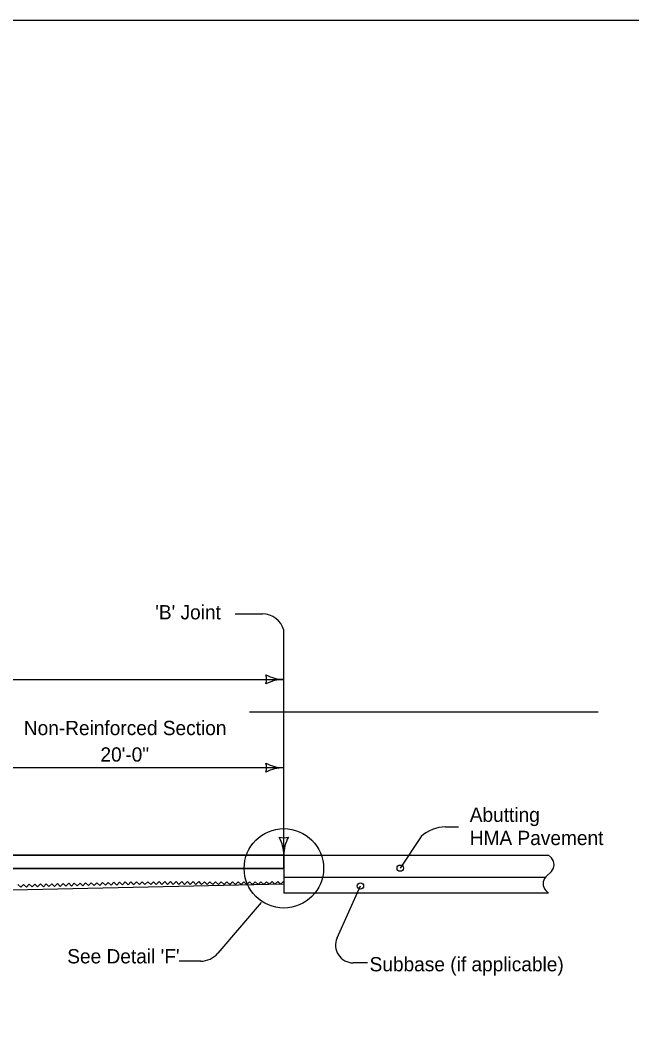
# Model space of a CAD drawing. Extents: x -2134934 to -2124557, y -2139046 to -2134021.
# Drawn here: x -2130115 to -2129429, y -2138178 to -2137036 of the extents above; entities that cross this region are included whole.
import ezdxf

# ---------------------------------------------------------------- set-up
doc = ezdxf.new("R2010")
doc.units = 0
for name, color, linetype in [('BridgeSuperStructureExisting', 7, 'Continuous'), ('dsnAlignmentStation', 7, 'Continuous'), ('dsnStdLabel', 7, 'Continuous'), ('TC_Barrier', 7, 'Continuous')]:
    doc.layers.add(name, color=color, linetype=linetype)

msp = doc.modelspace()

# ---------------------------------------------------------------- linework, layer by layer
at = {"layer": 'BridgeSuperStructureExisting'}
for p, q in [((-2129873.6, -2137701.5), (-2129843.1, -2137701.5)), ((-2129819.2, -2137972.1), (-2129819.2, -2137719.8)), ((-2130980.5, -2137775), (-2129819.2, -2137775)), ((-2129857.8, -2137811.5), (-2129466.9, -2137811.5)), ((-2130175.6, -2137874), (-2129819.2, -2137874)), ((-2129638.1, -2137940.5), (-2129623.3, -2137940.5)), ((-2129665.1, -2137951.1), (-2129688.8, -2137986.7)), ((-2130977.5, -2137972.1), (-2129819.2, -2137972.1)), ((-2129819.2, -2137972.1), (-2130175.6, -2137972.1)), ((-2129819.2, -2137986.9), (-2129819.2, -2137972.1)), ((-2129819.2, -2137972.1), (-2129522.4, -2137972.1)), ((-2129819.2, -2137972.1), (-2129819.2, -2137986.9)), ((-2129537, -2137972.1), (-2129537, -2137972.1)), ((-2129519.3, -2137975.2), (-2129522.4, -2137972.1)), ((-2129819.2, -2137986.9), (-2130977.5, -2137986.9)), ((-2130175.6, -2137986.9), (-2129819.2, -2137986.9)), ((-2129819.2, -2137986.9), (-2129819.2, -2138014.6)), ((-2129819.2, -2137996.8), (-2129525.8, -2137996.8)), ((-2129525.6, -2137996.6), (-2129519.3, -2137990.3)), ((-2129819.2, -2138004.6), (-2130943.9, -2138030)), ((-2129759.6, -2138065), (-2129733.3, -2138006.7)), ((-2129522.4, -2138014.8), (-2129525.6, -2138011.7)), ((-2129522.6, -2138014.6), (-2129819.2, -2138014.6)), ((-2129844.7, -2138025.1), (-2129893.3, -2138082.2)), ((-2129912.4, -2138091), (-2129936.6, -2138091)), ((-2129725.3, -2138092.9), (-2129741.5, -2138092.9))]:
    msp.add_line(p, q, dxfattribs=at)
for points in [[(-2130117.4, -2138005), (-2130114.2, -2138008.1), (-2130111.1, -2138004.9), (-2130107.8, -2138008), (-2130104.7, -2138004.7), (-2130101.5, -2138007.8), (-2130098.4, -2138004.6), (-2130095.2, -2138007.7), (-2130092.1, -2138004.4), (-2130088.8, -2138007.5), (-2130085.7, -2138004.3), (-2130082.5, -2138007.4), (-2130079.4, -2138004.1), (-2130076.2, -2138007.2), (-2130073.1, -2138004), (-2130069.8, -2138007.1), (-2130066.7, -2138003.8), (-2130065.1, -2138005.4)], [(-2130065.1, -2138005.4), (-2130063.5, -2138006.9), (-2130060.4, -2138003.7), (-2130057.2, -2138006.8), (-2130054.1, -2138003.5), (-2130050.8, -2138006.6), (-2130047.7, -2138003.4), (-2130044.5, -2138006.5), (-2130041.4, -2138003.2), (-2130038.2, -2138006.3), (-2130035.1, -2138003.1), (-2130031.8, -2138006.2), (-2130028.7, -2138003), (-2130025.5, -2138006), (-2130022.4, -2138002.8), (-2130019.2, -2138005.9), (-2130016.1, -2138002.7), (-2130012.8, -2138005.7), (-2130009.7, -2138002.5), (-2130006.5, -2138005.6), (-2130003.4, -2138002.4), (-2130000.2, -2138005.4), (-2129997.1, -2138002.2), (-2129993.8, -2138005.3), (-2129990.7, -2138002.1), (-2129989.1, -2138003.6)], [(-2129989.1, -2138003.5), (-2129987.5, -2138005), (-2129984.4, -2138001.9), (-2129981.2, -2138005), (-2129978, -2138001.9), (-2129974.9, -2138005), (-2129971.7, -2138001.9), (-2129968.5, -2138005), (-2129965.4, -2138001.9), (-2129962.2, -2138005), (-2129959, -2138001.8), (-2129955.9, -2138005), (-2129952.7, -2138001.8), (-2129949.5, -2138005), (-2129946.4, -2138001.8), (-2129943.2, -2138005), (-2129940, -2138001.8), (-2129936.8, -2138005), (-2129933.7, -2138001.8), (-2129930.5, -2138005), (-2129927.3, -2138001.8), (-2129924.2, -2138005), (-2129921, -2138001.8), (-2129917.8, -2138005), (-2129914.7, -2138001.8), (-2129913.1, -2138003.4)], [(-2129913.1, -2138003.6), (-2129911.5, -2138005.2), (-2129908.3, -2138002), (-2129905.2, -2138005.2), (-2129902, -2138002), (-2129898.8, -2138005.2), (-2129895.7, -2138002), (-2129892.5, -2138005.2), (-2129889.3, -2138002), (-2129886.2, -2138005.1), (-2129883, -2138002), (-2129879.8, -2138005.1), (-2129876.7, -2138002), (-2129873.5, -2138005.1), (-2129870.3, -2138002), (-2129867.1, -2138005.1), (-2129864, -2138002), (-2129860.8, -2138005.1), (-2129857.6, -2138001.9), (-2129854.5, -2138005.1), (-2129851.3, -2138001.9), (-2129848.1, -2138005.1), (-2129845, -2138001.9), (-2129841.8, -2138005.1), (-2129838.6, -2138001.9), (-2129837.1, -2138003.5)], [(-2129837.1, -2138003.2), (-2129835.5, -2138004.7), (-2129832.3, -2138001.6), (-2129829.2, -2138004.7), (-2129826, -2138001.6), (-2129822.8, -2138004.7), (-2129819.7, -2138001.6), (-2129819.2, -2138002)]]:
    msp.add_lwpolyline(points, dxfattribs=at)
msp.add_circle((-2129819.2, -2137986.9), 44.5, dxfattribs=at)
for centre, radius, start, end in [((-2129843.1, -2137726.2), 24.7, 15.0299, 90), ((-2129855.1, -2137775), 16.5, 342.2666, 17.7333), ((-2129819.2, -2137732.3), 42.7, 241.9275, 270), ((-2129819.2, -2137817.8), 42.7, 90, 118.0725), ((-2129855.1, -2137874), 16.5, 342.2666, 17.7333), ((-2129819.2, -2137831.3), 42.7, 241.9275, 270), ((-2129819.2, -2137916.8), 42.7, 90, 118.0725), ((-2129638.1, -2137980.1), 39.6, 90, 132.998), ((-2129819.2, -2137936.2), 16.5, 252.2666, 287.7333), ((-2129862, -2137972.1), 42.7, 360, 28.0725), ((-2129776.5, -2137972.1), 42.7, 151.9275, 180), ((-2129526.9, -2137982.8), 10.7, 315, 45), ((-2129518, -2138004.1), 10.7, 135, 225), ((-2129741.5, -2138073.1), 19.8, 155.762, 270), ((-2129912.4, -2138066), 25, 270, 319.6052)]:
    msp.add_arc(centre, radius, start, end, dxfattribs=at)
at = {"layer": 'dsnAlignmentStation'}
msp.add_lwpolyline([(-2131334.4, -2137035.9), (-2128199.4, -2137035.9), (-2128199.4, -2139045.9), (-2131334.4, -2139045.9)], close=True, dxfattribs=at)
at = {"layer": 'TC_Barrier'}
for centre in [(-2129688.8, -2137986.7), (-2129733.3, -2138006.7)]:
    msp.add_circle(centre, 3.54, dxfattribs=at)

# ---------------------------------------------------------------- texts
at = {"layer": 'dsnStdLabel'}
for s, p in [("'B' Joint", (-2129963.4, -2137707.7)), ('Non-Reinforced Section', (-2130110.7, -2137837.5)), ('20\'-0"', (-2130024.8, -2137867.2)), ('Abutting', (-2129610.8, -2137934.8)), ('HMA Pavement', (-2129610.8, -2137960.8)), ("See Detail 'F'", (-2130062, -2138093.5)), ('Subbase (if applicable)', (-2129723.1, -2138102.4))]:
    msp.add_text(s, height=16, dxfattribs=at).set_placement(p)

doc.saveas('drawing.dxf')
